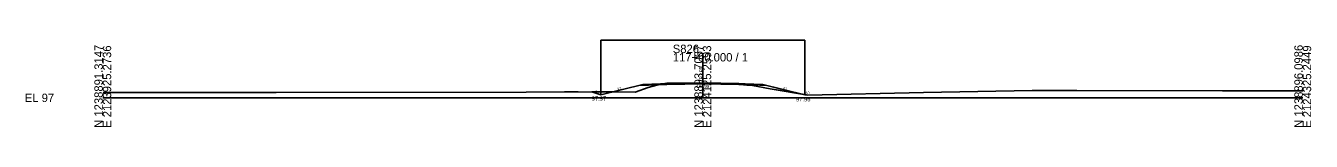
# Model space of a CAD drawing. Extents: x 2119282 to 2119710, y 1215030 to 1220057.
# Drawn here: x 2119281.9 to 2119710.4, y 1215530.1 to 1215559.1 of the extents above; entities that cross this region are included whole.
import ezdxf

# ---------------------------------------------------------------- set-up
doc = ezdxf.new("R2010")
doc.units = 0
for name, color, linetype in [('XS_CELL', 7, 'Continuous'), ('XS_M_DITCH', 7, 'Continuous'), ('XS_M_SHAPES_EARTHWORK', 7, 'Continuous'), ('XS_P_FINISHED_GRADE', 7, 'Continuous'), ('XS_P_FINISHED_GRADE_ELEV_TX', 7, 'Continuous'), ('XS_P_SUBGRADE_GRANULAR', 7, 'Continuous'), ('XS_P_SUBGRADE_PAVEMENT', 7, 'Continuous'), ('XS_P_TX_DCH', 7, 'Continuous'), ('XS_P_TX_FS_BS', 7, 'Continuous'), ('XS_X_GROUND', 7, 'Continuous'), ('XS_X_GROUND_TX', 7, 'Continuous')]:
    doc.layers.add(name, color=color, linetype=linetype)

msp = doc.modelspace()

# ---------------------------------------------------------------- linework, layer by layer
at = {"layer": 'XS_CELL'}
for p, q in [((2119507.6, 1215539.8), (2119507.6, 1215554.74)), ((2119307.6, 1215539.8), (2119507.6, 1215539.8)), ((2119507.6, 1215539.8), (2119707.6, 1215539.8))]:
    msp.add_line(p, q, dxfattribs=at)
at = {"layer": 'XS_M_DITCH'}
for p, q in [((2119473.6, 1215540.77), (2119473.6, 1215559.07)), ((2119473.6, 1215559.07), (2119541.6, 1215559.07)), ((2119541.6, 1215540.76), (2119541.6, 1215559.07))]:
    msp.add_line(p, q, dxfattribs=at)
at = {"layer": 'XS_M_SHAPES_EARTHWORK'}
for p, q in [((2119470.6, 1215541.77), (2119473.6, 1215540.77)), ((2119477.57, 1215541.76), (2119470.6, 1215541.77)), ((2119473.6, 1215540.77), (2119477.57, 1215541.76)), ((2119486.25, 1215543.93), (2119477.57, 1215541.76)), ((2119477.57, 1215541.76), (2119485.01, 1215541.75)), ((2119485.01, 1215541.75), (2119489.38, 1215543.2)), ((2119492.76, 1215544.19), (2119486.25, 1215543.93)), ((2119489.38, 1215543.2), (2119492.76, 1215544.19)), ((2119493.42, 1215544.38), (2119492.76, 1215544.19)), ((2119492.76, 1215544.19), (2119493.17, 1215544.2)), ((2119493.42, 1215544.38), (2119493.17, 1215544.2)), ((2119493.17, 1215544.2), (2119493.42, 1215544.38)), ((2119493.17, 1215544.2), (2119495.6, 1215544.25)), ((2119493.82, 1215544.49), (2119493.42, 1215544.38)), ((2119493.95, 1215544.51), (2119493.82, 1215544.49)), ((2119494.93, 1215544.62), (2119493.95, 1215544.51)), ((2119495.6, 1215544.54), (2119493.95, 1215544.51)), ((2119493.95, 1215544.51), (2119495.6, 1215544.54)), ((2119495.6, 1215544.68), (2119494.93, 1215544.62)), ((2119495.6, 1215544.54), (2119495.6, 1215544.68)), ((2119520.44, 1215544.23), (2119519.6, 1215544.32)), ((2119519.6, 1215544.32), (2119519.6, 1215544.25)), ((2119519.6, 1215544.25), (2119520.44, 1215544.23)), ((2119522.04, 1215544.2), (2119520.44, 1215544.23)), ((2119520.44, 1215544.23), (2119522.29, 1215544.05)), ((2119528.95, 1215543.93), (2119522.04, 1215544.2)), ((2119522.29, 1215544.05), (2119524.14, 1215543.9)), ((2119524.14, 1215543.9), (2119530.1, 1215542.86)), ((2119539.74, 1215541.23), (2119528.95, 1215543.93)), ((2119530.1, 1215542.86), (2119539.74, 1215541.23)), ((2119541.9, 1215540.86), (2119539.74, 1215541.23)), ((2119539.74, 1215541.23), (2119541.6, 1215540.76)), ((2119541.6, 1215540.76), (2119541.9, 1215540.86))]:
    msp.add_line(p, q, dxfattribs=at)
msp.add_lwpolyline([(2119495.6, 1215544.25), (2119495.6, 1215544.25), (2119495.6, 1215544.54)], dxfattribs=at)
at = {"layer": 'XS_P_FINISHED_GRADE'}
for p, q in [((2119473.6, 1215540.77), (2119470.6, 1215541.77)), ((2119487.6, 1215544.26), (2119473.6, 1215540.77)), ((2119493.6, 1215544.5), (2119487.6, 1215544.26)), ((2119495.6, 1215544.54), (2119493.6, 1215544.5)), ((2119507.6, 1215544.78), (2119495.6, 1215544.54)), ((2119507.6, 1215544.78), (2119519.6, 1215544.54)), ((2119519.6, 1215544.54), (2119521.6, 1215544.5)), ((2119521.6, 1215544.5), (2119527.6, 1215544.26)), ((2119527.6, 1215544.26), (2119541.6, 1215540.76)), ((2119541.6, 1215540.76), (2119541.9, 1215540.86))]:
    msp.add_line(p, q, dxfattribs=at)
at = {"layer": 'XS_P_SUBGRADE_GRANULAR'}
for p, q in [((2119493.17, 1215544.2), (2119486.25, 1215543.93)), ((2119522.04, 1215544.2), (2119528.95, 1215543.93))]:
    msp.add_line(p, q, dxfattribs=at)
at = {"layer": 'XS_P_SUBGRADE_PAVEMENT'}
for p, q in [((2119493.6, 1215544.5), (2119493.17, 1215544.2)), ((2119495.61, 1215544.25), (2119493.17, 1215544.2)), ((2119507.6, 1215544.49), (2119495.61, 1215544.25)), ((2119507.6, 1215544.49), (2119519.6, 1215544.25)), ((2119519.6, 1215544.25), (2119522.04, 1215544.2)), ((2119521.6, 1215544.5), (2119522.04, 1215544.2))]:
    msp.add_line(p, q, dxfattribs=at)
at = {"layer": 'XS_X_GROUND'}
for p, q in [((2119307.75, 1215541.54), (2119345.55, 1215541.61)), ((2119345.55, 1215541.61), (2119365.43, 1215541.62)), ((2119365.43, 1215541.62), (2119448.78, 1215541.74)), ((2119448.78, 1215541.74), (2119461.55, 1215541.76)), ((2119461.55, 1215541.76), (2119466.09, 1215541.77)), ((2119466.09, 1215541.77), (2119485.01, 1215541.75)), ((2119485.01, 1215541.75), (2119489.38, 1215543.2)), ((2119489.38, 1215543.2), (2119493.82, 1215544.49)), ((2119493.82, 1215544.49), (2119494.93, 1215544.62)), ((2119494.93, 1215544.62), (2119495.69, 1215544.68)), ((2119495.69, 1215544.68), (2119503.25, 1215544.73)), ((2119503.25, 1215544.73), (2119507.6, 1215544.78)), ((2119507.6, 1215544.78), (2119511.93, 1215544.61)), ((2119511.93, 1215544.61), (2119518.98, 1215544.38)), ((2119518.98, 1215544.38), (2119522.29, 1215544.05)), ((2119522.29, 1215544.05), (2119524.14, 1215543.9)), ((2119524.14, 1215543.9), (2119530.1, 1215542.86)), ((2119530.1, 1215542.86), (2119542.6, 1215540.74)), ((2119542.6, 1215540.74), (2119581.19, 1215541.55)), ((2119581.19, 1215541.55), (2119617.4, 1215542.23)), ((2119617.4, 1215542.23), (2119632.26, 1215542.23)), ((2119632.26, 1215542.23), (2119680.85, 1215542.19)), ((2119680.85, 1215542.19), (2119705.37, 1215542.15)), ((2119705.37, 1215542.15), (2119707.75, 1215542.13))]:
    msp.add_line(p, q, dxfattribs=at)

# ---------------------------------------------------------------- texts
at = {"layer": 'XS_CELL'}
for s, p in [('N 1238891.3147', (2119307.6, 1215529.8)), ('E 2123925.2736', (2119310.4, 1215529.8)), ('N 1238893.7067', (2119507.6, 1215529.8)), ('E 2124125.2593', (2119510.4, 1215529.8)), ('N 1238896.0986', (2119707.6, 1215529.8)), ('E 2124325.2449', (2119710.4, 1215529.8))]:
    msp.add_text(s, height=2.8, rotation=90, dxfattribs=at).set_placement(p)
for s, p in [('S826', (2119497.6, 1215554.74)), ('117+00.000 / 1', (2119497.6, 1215551.94)), ('EL 97', (2119281.6, 1215538.4))]:
    msp.add_text(s, height=2.8, dxfattribs=at).set_placement(p)
at = {"layer": 'XS_P_FINISHED_GRADE_ELEV_TX'}
msp.add_text('101.98', height=1.25, rotation=90, dxfattribs=at).set_placement((2119507.6, 1215545.02))
at = {"layer": 'XS_P_TX_DCH'}
for s, p in [('97.97', (2119470.59, 1215538.86)), ('97.96', (2119538.66, 1215538.61))]:
    msp.add_text(s, height=1.4, dxfattribs=at).set_placement(p)
at = {"layer": 'XS_P_TX_FS_BS'}
for s, rotation, p in [('3:1', 341.5921, (2119471.67, 1215541.53)), ('4:1', 14.015, (2119479.11, 1215542.38)), ('4:1', 345.9638, (2119534.27, 1215542.75)), ('3:1', 18.4349, (2119541.97, 1215540.94))]:
    msp.add_text(s, height=0.8, rotation=rotation, dxfattribs=at).set_placement(p)
at = {"layer": 'XS_X_GROUND_TX'}
msp.add_text('101.98', height=1, dxfattribs=at).set_placement((2119505.47, 1215543.12))

doc.saveas('drawing.dxf')
